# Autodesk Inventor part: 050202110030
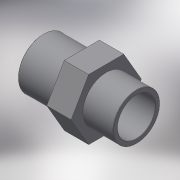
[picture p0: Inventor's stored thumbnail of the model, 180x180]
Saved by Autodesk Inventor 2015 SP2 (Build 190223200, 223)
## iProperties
Created: 2017-10
Part Number: 050202110030
Material: Generic
Description: PLASSON REDUCER THR-CEM PVC 110(90)3"F
Document SubType Name: Modeling
Designer: KIM
Density: 1 g/cm^3
Appearance: Default
Author: KIM
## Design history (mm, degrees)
derived "050202.ipt"
feature "Solid1::050202.ipt"
tag "TaggingFeature1"
body "Solid1"
other parameters: "d0" = 106, "d3" = 84.926, "d4" = 81, "d6" = 33, "d8" = 103.5, "d13" = 0, "d14" = 0.9, "d17" = 61, "d18" = 39.6, "G_" = 84.926, "L_" = 61, "lt_" = 33, "H_" = 106
